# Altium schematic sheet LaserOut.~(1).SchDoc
size A
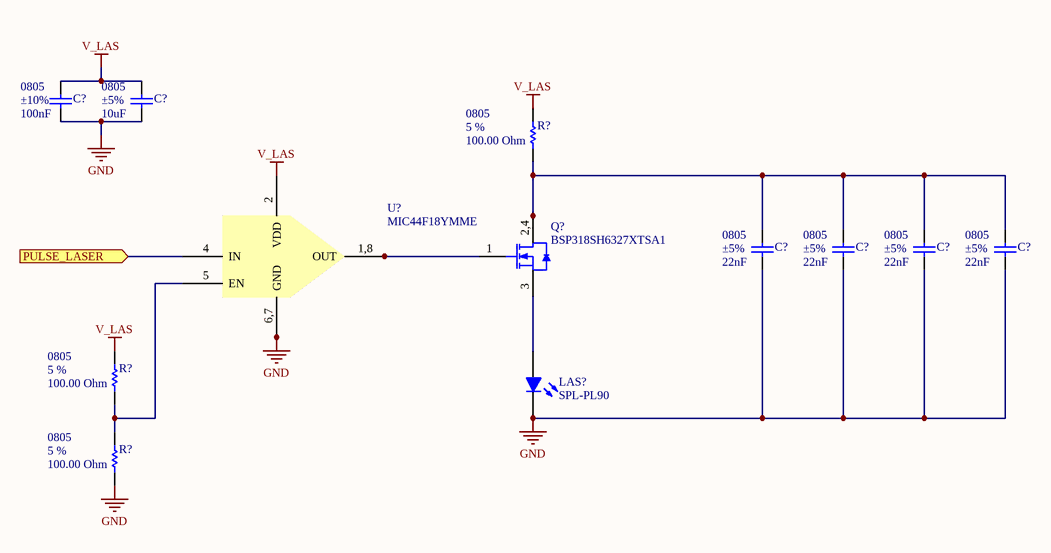
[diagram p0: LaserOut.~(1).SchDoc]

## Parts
(Parts that share a designator on the sheet are numbered #1, #2 ... from top to bottom, then left to right.)
C?#1  value 100nF  Case-EIA: 0805  Tolerance: ±10%  [CAPC0805(2012)100_N]  (hidden comment: CAP 100nF 6.3V 0805(2012))
C?#2  value 10uF  Case-EIA: 0805  Tolerance: ±5%  [CAPC0805(2012)145_N]  (hidden comment: CAP 10uF 6.3V 0805(2012))
C?#3  value 22nF  Case-EIA: 0805  Tolerance: ±5%  [CAPC0805(2012)100_L]  (hidden comment: CAP 22nF 6.3V 0805(2012))
C?#4  value 22nF  Case-EIA: 0805  Tolerance: ±5%  [CAPC0805(2012)100_L]  (hidden comment: CAP 22nF 6.3V 0805(2012))
C?#5  value 22nF  Case-EIA: 0805  Tolerance: ±5%  [CAPC0805(2012)100_L]  (hidden comment: CAP 22nF 6.3V 0805(2012))
C?#6  value 22nF  Case-EIA: 0805  Tolerance: ±5%  [CAPC0805(2012)100_L]  (hidden comment: CAP 22nF 6.3V 0805(2012))
LAS?  SPL-PL90
Q?  BSP318SH6327XTSA1
R?#1  value 100.00 Ohm  Case-EIA: 0805  Tolerance: 5 %  [RESC0805(2012)_M]  (hidden comment: 100R 5% 0805(2012))
R?#2  value 100.00 Ohm  Case-EIA: 0805  Tolerance: 5 %  [RESC0805(2012)_M]  (hidden comment: 100R 5% 0805(2012))
R?#3  value 100.00 Ohm  Case-EIA: 0805  Tolerance: 5 %  [RESC0805(2012)_M]  (hidden comment: 100R 5% 0805(2012))
U?  MIC44F18YMME

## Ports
PULSE_LASER (in)

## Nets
GND: C?#1.1 C?#2.1 C?#3.1 C?#4.1 C?#5.1 C?#6.1 LAS?.2(K) R?#3.1 U?.6(GND) U?.7(GND)
V_LAS: C?#1.2 C?#2.2 R?#1.2 R?#2.2 U?.2(VDD)
PULSE_LASER: U?.4(IN) ; port PULSE_LASER
NetC?#3_2: C?#3.2 C?#4.2 C?#5.2 C?#6.2 Q?.2(D) Q?.4(D) R?#1.1
NetLAS?_1: LAS?.1(A) Q?.3(S)
NetQ?_1: Q?.1(G) U?.1(OUT) U?.8(OUT)
NetR?#2_1: R?#2.1 R?#3.2 U?.5(EN)

Not connected (* = marked no-connect by the designer): U? 3(NC)

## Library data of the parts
C?#1 = CMP-1036-04391-1: CAP 100nF 6.3V ±10% 0805 (2012 Metric) Thickness 1mm SMD; Case-Metric: 2012
C?#2 = CMP-1036-04781-1: CAP 10uF 6.3V ±5% 0805 (2012 Metric) Thickness 1.45mm SMD; Case-Metric: 2012
C?#3-C?#6 = CMP-1036-04030-1: CAP 22nF 6.3V ±5% 0805 (2012 Metric) Thickness 1mm SMD; Case-Metric: 2012
Q? = BSP318SH6327XTSA1: MOSFET N-Ch 60V 2.6A SOT-223-3
R?#1-R?#3 = CMP-1013-00050-1: 100R 0.125W 5% 0805 (2012 Metric)  SMD; Case-Metric: 2012
U? = MIC44F18YMME: Gate Drivers 3A High Speed MOSFET Driver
